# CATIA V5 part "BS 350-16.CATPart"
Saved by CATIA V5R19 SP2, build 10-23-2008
Part number: BS 300-16
Bounding box of the stored display mesh (mm): x -15.868 to 15.868, y -15.868 to 15.868, z 0 to 62
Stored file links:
  C:\Users\Bora\Desktop\3D Katı model\BS serisi\BS 300\BS 300-16.CATPart
  C:\Program Files\Dassault Systemes\B19\intel_a\reffiles\standard\MetricThickPitch.txt
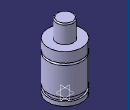
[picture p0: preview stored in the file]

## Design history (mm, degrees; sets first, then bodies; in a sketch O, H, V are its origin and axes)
Body1 (main body)
  Sketch1 on yz-plane, origin (0, 0, 0), H (0, 1, 0), V (0, 0, 1)
    point P1 (8, 61)
    point P3 (8, 61)
    point P5 (16, 35.5)
    point P6 (16, 33.5)
    point P9 (16, 35.5)
    point P14 (16, 33.5)
    line L1 (8, 61) -> (8, 45)
    arc A1 centre (7, 61) radius 1 from (8, 61) to (7, 62) ccw
    arc A2 centre (16, 34.5) radius 1 from (16, 35.5) to (16, 33.5) ccw
    line L2 (16, 0) -> (16, 4)
    line L3 (16, 35.5) -> (16, 45)
    line L4 (14.5, 7.5) -> (14.5, 4)
    line L5 (16, 7.5) -> (16, 33.5)
    line L6 (7, 62) -> (0, 62)
    point P15 (0, 62)
    line L7 (8, 45) -> (16, 45)
    line L8 (0, 0) -> (16, 0)
    line L9 (14.5, 7.5) -> (16, 7.5)
    line L10 (14.5, 4) -> (16, 4)
    coincidence: P15 V, P1 P3, P5 P9, P6 P14
    tangency: L6 A1
    horizontal: L7 H, L8 H, L9 H, L10 H
  Shaft1: profile Sketch1, axis Sketch1.V, angle 360
  Sketch2 on face of Shaft1 from Sketch1.L8, origin (0, 0, 0), H (1, 0, 0), V (0, -1, 0)
    point P1 (0, 0)
  Hole1: placed by Sketch2, at (0, 0, 0) direction (0, 0, 1), diameter 6.647, depth 4, threaded "M8", thread diameter 8, thread depth 4, pitch 1.25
